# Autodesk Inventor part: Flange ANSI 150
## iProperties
Created: 2006-06
Part Number: Flange ANSI 150
Document SubType Name: Modeling
Designer: Ennio
Author: Ennio
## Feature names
1. Estrusione1 [Extrusion]
2. Estrusione2 [Extrusion]
3. Estrusione8 [Extrusion]
4. Serie circolare3 [Circular Pattern]
5. Estrusione9 [Extrusion]
6. Rivoluzione1 [Revolution]
